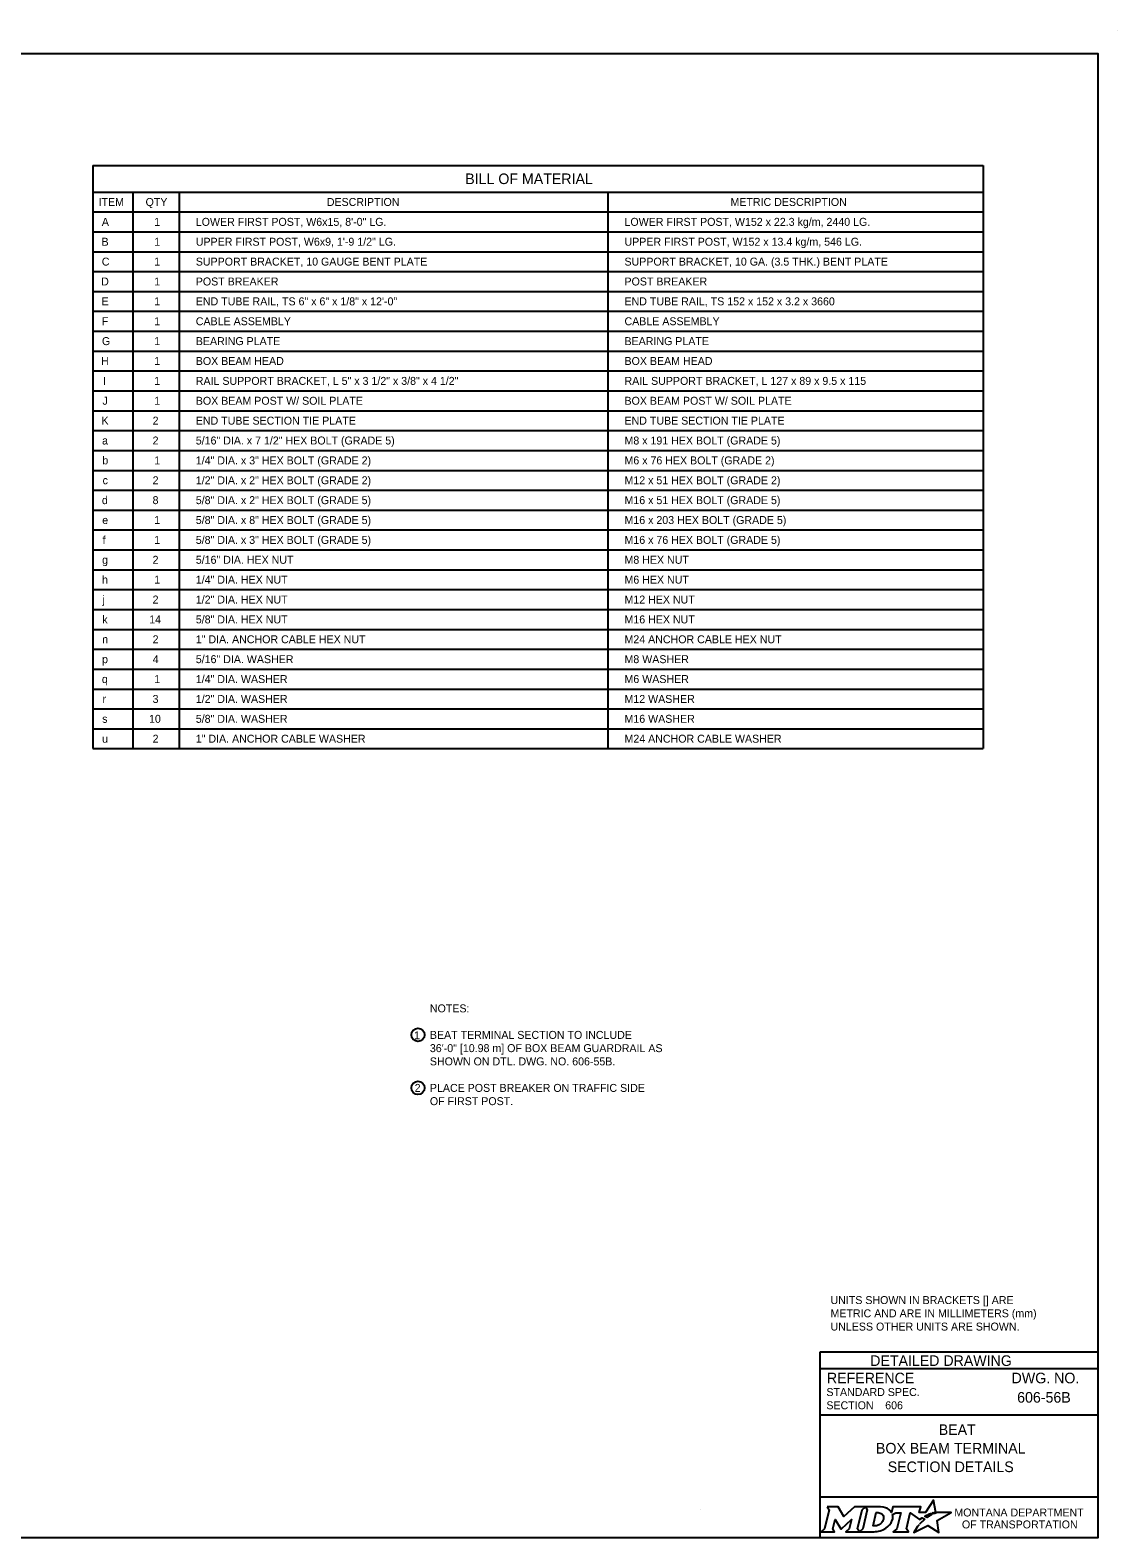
# Model space of a CAD drawing. Extents: x 49991.4 to 50021, y 49987.6 to 50011.4.
# Drawn here: x 50008.69 to 50016.9, y 49987.8 to 49999.18 of the extents above; entities that cross this region are included whole.
import ezdxf

# ---------------------------------------------------------------- set-up
doc = ezdxf.new("R2010")
doc.units = 0
for name, color, linetype in [('Default', 7, 'Continuous'), ('Level 1', 7, 'Continuous'), ('Level 2', 7, 'Continuous'), ('Level 5', 7, 'Continuous')]:
    doc.layers.add(name, color=color, linetype=linetype)

msp = doc.modelspace()

# ---------------------------------------------------------------- linework, layer by layer
at = {"layer": 'Default'}
for points in [[(50015.513, 49987.981), (50015.502, 49987.987), (50015.514, 49987.99), (50015.526, 49987.991), (50015.508, 49988.082), (50015.449, 49987.99), (50015.401, 49987.99), (50015.412, 49988.034), (50015.202, 49988.034), (50015.192, 49987.991), (50015.186, 49988)], [(50014.706, 49988.034), (50014.72, 49988.01), (50014.686, 49987.867), (50014.66, 49987.845), (50014.762, 49987.845), (50014.749, 49987.867), (50014.765, 49987.937), (50014.809, 49987.868), (50014.814, 49987.868), (50014.889, 49987.938), (50014.872, 49987.867), (50014.848, 49987.845), (50014.949, 49987.845), (50014.936, 49987.868), (50014.969, 49988.011)], [(50014.969, 49988.011), (50014.994, 49988.034), (50014.912, 49988.034), (50014.832, 49987.961), (50014.788, 49988.034), (50014.706, 49988.034)], [(50015.108, 49988.034), (50014.994, 49988.034), (50015.009, 49988.011), (50014.975, 49987.867), (50014.949, 49987.845), (50015.06, 49987.845)], [(50015.132, 49987.947), (50015.13, 49987.939), (50015.127, 49987.93), (50015.123, 49987.922), (50015.118, 49987.914), (50015.111, 49987.907), (50015.103, 49987.901), (50015.095, 49987.896), (50015.086, 49987.892), (50015.077, 49987.89), (50015.067, 49987.889), (50015.052, 49987.889), (50015.075, 49987.989), (50015.091, 49987.989), (50015.099, 49987.988), (50015.106, 49987.986), (50015.113, 49987.983), (50015.119, 49987.979), (50015.124, 49987.974), (50015.128, 49987.968), (50015.13, 49987.962), (50015.132, 49987.955), (50015.132, 49987.952), (50015.132, 49987.947)], [(50015.199, 49987.975), (50015.224, 49987.988), (50015.261, 49987.988), (50015.232, 49987.867), (50015.205, 49987.845), (50015.321, 49987.845), (50015.304, 49987.867), (50015.332, 49987.988), (50015.403, 49987.936), (50015.424, 49987.951), (50015.444, 49987.94)], [(50015.388, 49987.884), (50015.373, 49987.86), (50015.368, 49987.852), (50015.362, 49987.844), (50015.36, 49987.839), (50015.465, 49987.893), (50015.549, 49987.838), (50015.536, 49987.93), (50015.643, 49987.989), (50015.594, 49987.989), (50015.564, 49987.99), (50015.543, 49987.99), (50015.536, 49987.989), (50015.531, 49987.987), (50015.523, 49987.985), (50015.513, 49987.981)], [(50015.462, 49987.954), (50015.46, 49987.952), (50015.442, 49987.961), (50015.452, 49987.967), (50015.456, 49987.969), (50015.465, 49987.973), (50015.47, 49987.976), (50015.478, 49987.979), (50015.485, 49987.982), (50015.497, 49987.974), (50015.493, 49987.972), (50015.489, 49987.97), (50015.484, 49987.967), (50015.479, 49987.965), (50015.478, 49987.963), (50015.475, 49987.962), (50015.472, 49987.96), (50015.47, 49987.959), (50015.467, 49987.957), (50015.465, 49987.955), (50015.462, 49987.954)], [(50015.106, 49987.852), (50015.114, 49987.855), (50015.127, 49987.86), (50015.148, 49987.871)], [(50015.402, 49987.9), (50015.402, 49987.9)]]:
    msp.add_lwpolyline(points, dxfattribs=at)
for centre, radius, start, end in [((50015.087, 49987.973), 0.118, 300.9103, 339.1383), ((50015.131, 49987.955), 0.0709, 339.5329, 15.8582)]:
    msp.add_arc(centre, radius, start, end, dxfattribs=at)
for centre, major_axis, ratio, start_param, end_param in [((50015.106, 49987.986), (0.0834, -0.0037), 0.568097, 0.61298, 1.570796), ((50015.161, 49987.994), (0.0361, -0.0295), 0.469099, 1.225588, 1.570796), ((50015.433, 49987.93), (-0.0112, -0.0097), 0.021651, 3.157348, 6.283185), ((50015.06, 49987.993), (0, 0.148), 0.987302, 3.139398, 3.456847), ((50015.395, 49987.892), (-0.00694, -0.00806), 0.008222, 0, 3.137361), ((50015.412, 49987.911), (-0.0098, -0.0102), 0.016458, 3.141593, 6.279097)]:
    msp.add_ellipse(centre, major_axis=major_axis, ratio=ratio, start_param=start_param, end_param=end_param, dxfattribs=at)
at = {"layer": 'Level 1'}
msp.add_line((50016.9, 49999.176), (50016.9, 49999.176), dxfattribs=at)
msp.add_lwpolyline([(49999.384, 49998.999), (50016.75, 49998.999), (50016.75, 49987.799), (49999.384, 49987.799)], close=True, dxfattribs=at)
at = {"layer": 'Level 2'}
for p, q in [((50009.164, 49998.154), (50009.164, 49993.754)), ((50009.164, 49998.154), (50015.883, 49998.154)), ((50015.883, 49998.154), (50015.883, 49993.754)), ((50009.164, 49997.954), (50013.049, 49997.954)), ((50009.464, 49997.954), (50009.464, 49993.754)), ((50009.814, 49997.954), (50009.814, 49993.754)), ((50013.049, 49997.954), (50015.883, 49997.954)), ((50013.049, 49997.954), (50013.049, 49993.754)), ((50009.164, 49997.804), (50013.049, 49997.804)), ((50013.049, 49997.804), (50015.883, 49997.804)), ((50009.164, 49997.654), (50013.049, 49997.654)), ((50013.049, 49997.654), (50015.883, 49997.654)), ((50009.164, 49997.504), (50013.049, 49997.504)), ((50013.049, 49997.504), (50015.883, 49997.504)), ((50009.164, 49997.354), (50013.049, 49997.354)), ((50013.049, 49997.354), (50015.883, 49997.354)), ((50009.164, 49997.204), (50013.049, 49997.204)), ((50013.049, 49997.204), (50015.883, 49997.204)), ((50009.164, 49997.054), (50013.049, 49997.054)), ((50013.049, 49997.054), (50015.883, 49997.054)), ((50009.164, 49996.904), (50013.049, 49996.904)), ((50013.049, 49996.904), (50015.883, 49996.904)), ((50009.164, 49996.754), (50013.049, 49996.754)), ((50013.049, 49996.754), (50015.883, 49996.754)), ((50009.164, 49996.604), (50013.049, 49996.604)), ((50013.049, 49996.604), (50015.883, 49996.604)), ((50009.164, 49996.454), (50013.049, 49996.454)), ((50013.049, 49996.454), (50015.883, 49996.454)), ((50009.164, 49996.304), (50013.049, 49996.304)), ((50013.049, 49996.304), (50015.883, 49996.304)), ((50009.164, 49996.154), (50013.049, 49996.154)), ((50013.049, 49996.154), (50015.883, 49996.154)), ((50009.164, 49996.004), (50013.049, 49996.004)), ((50013.049, 49996.004), (50015.883, 49996.004)), ((50009.164, 49995.854), (50013.049, 49995.854)), ((50013.049, 49995.854), (50015.883, 49995.854)), ((50009.164, 49995.704), (50013.049, 49995.704)), ((50013.049, 49995.704), (50015.883, 49995.704)), ((50009.164, 49995.554), (50013.049, 49995.554)), ((50013.049, 49995.554), (50015.883, 49995.554)), ((50009.164, 49995.404), (50013.049, 49995.404)), ((50013.049, 49995.404), (50015.883, 49995.404)), ((50009.164, 49995.254), (50013.049, 49995.254)), ((50013.049, 49995.254), (50015.883, 49995.254)), ((50009.164, 49995.104), (50013.049, 49995.104)), ((50013.049, 49995.104), (50015.883, 49995.104)), ((50009.164, 49994.954), (50013.049, 49994.954)), ((50013.049, 49994.954), (50015.883, 49994.954)), ((50009.164, 49994.804), (50013.049, 49994.804)), ((50013.049, 49994.804), (50015.883, 49994.804)), ((50009.164, 49994.654), (50013.049, 49994.654)), ((50013.049, 49994.654), (50015.883, 49994.654)), ((50009.164, 49994.504), (50013.049, 49994.504)), ((50013.049, 49994.504), (50015.883, 49994.504)), ((50009.164, 49994.354), (50013.049, 49994.354)), ((50013.049, 49994.354), (50015.883, 49994.354)), ((50009.164, 49994.204), (50013.049, 49994.204)), ((50013.049, 49994.204), (50015.883, 49994.204)), ((50009.164, 49994.054), (50013.049, 49994.054)), ((50013.049, 49994.054), (50015.883, 49994.054)), ((50009.164, 49993.904), (50013.049, 49993.904)), ((50013.049, 49993.904), (50015.883, 49993.904)), ((50009.164, 49993.754), (50013.049, 49993.754)), ((50013.049, 49993.754), (50015.883, 49993.754)), ((50013.746, 49988.012), (50013.746, 49988.012))]:
    msp.add_line(p, q, dxfattribs=at)
for centre in [(50011.617, 49991.594), (50011.617, 49991.194)]:
    msp.add_circle(centre, 0.05, dxfattribs=at)
at = {"layer": 'Level 5'}
for p, q in [((50016.75, 49989.199), (50014.65, 49989.199)), ((50014.65, 49989.199), (50014.65, 49987.799)), ((50016.75, 49989.074), (50014.65, 49989.074)), ((50016.386, 49988.859), (50016.386, 49988.859)), ((50016.75, 49988.724), (50014.65, 49988.724)), ((50015.144, 49988.799), (50015.144, 49988.799)), ((50015.7, 49988.475), (50015.7, 49988.475)), ((50016.75, 49988.106), (50014.65, 49988.106))]:
    msp.add_line(p, q, dxfattribs=at)

# ---------------------------------------------------------------- texts
at = {"layer": 'Default'}
for s, p in [('MONTANA DEPARTMENT', (50015.666, 49987.96)), ('OF TRANSPORTATION', (50015.723, 49987.87))]:
    msp.add_text(s, height=0.06, dxfattribs=at).set_placement(p)
at = {"layer": 'Level 2'}
for s, height, p in [('BILL OF MATERIAL', 0.08, (50011.974, 49998.014)), ('ITEM', 0.06, (50009.206, 49997.849)), ('QTY', 0.06, (50009.561, 49997.849)), ('DESCRIPTION', 0.06, (50010.929, 49997.849)), ('METRIC DESCRIPTION', 0.06, (50013.976, 49997.849)), ('  A', 0.06, (50009.186, 49997.699)), ('1', 0.06, (50009.626, 49997.699)), ('LOWER FIRST POST, W6x15, 8\'-0" LG.', 0.06, (50009.94, 49997.699)), ('LOWER FIRST POST, W152 x 22.3 kg/m, 2440 LG.', 0.06, (50013.176, 49997.699)), ('  B', 0.06, (50009.184, 49997.549)), ('1', 0.06, (50009.626, 49997.549)), ('UPPER FIRST POST, W6x9, 1\'-9 1/2" LG.', 0.06, (50009.94, 49997.549)), ('UPPER FIRST POST, W152 x 13.4 kg/m, 546 LG.', 0.06, (50013.176, 49997.549)), ('  C', 0.06, (50009.186, 49997.399)), ('1', 0.06, (50009.626, 49997.399)), ('SUPPORT BRACKET, 10 GAUGE BENT PLATE', 0.06, (50009.94, 49997.399)), ('SUPPORT BRACKET, 10 GA. (3.5 THK.) BENT PLATE', 0.06, (50013.176, 49997.399)), ('  D', 0.06, (50009.181, 49997.249)), ('1', 0.06, (50009.626, 49997.249)), ('POST BREAKER', 0.06, (50009.94, 49997.249)), ('POST BREAKER', 0.06, (50013.176, 49997.249)), ('  E', 0.06, (50009.184, 49997.099)), ('1', 0.06, (50009.626, 49997.099)), ('END TUBE RAIL, TS 6" x 6" x 1/8" x 12\'-0" ', 0.06, (50009.94, 49997.099)), ('END TUBE RAIL, TS 152 x 152 x 3.2 x 3660', 0.06, (50013.176, 49997.099)), ('  F', 0.06, (50009.186, 49996.949)), ('1', 0.06, (50009.626, 49996.949)), ('CABLE ASSEMBLY', 0.06, (50009.94, 49996.949)), ('CABLE ASSEMBLY', 0.06, (50013.176, 49996.949)), ('  G', 0.06, (50009.187, 49996.799)), ('1', 0.06, (50009.626, 49996.799)), ('BEARING PLATE', 0.06, (50009.94, 49996.799)), ('BEARING PLATE', 0.06, (50013.176, 49996.799)), ('  H', 0.06, (50009.18, 49996.649)), ('1', 0.06, (50009.626, 49996.649)), ('BOX BEAM HEAD', 0.06, (50009.94, 49996.649)), ('BOX BEAM HEAD', 0.06, (50013.176, 49996.649)), ('  I', 0.06, (50009.195, 49996.499)), ('1', 0.06, (50009.626, 49996.499)), ('RAIL SUPPORT BRACKET, L 5" x 3 1/2" x 3/8" x 4 1/2"', 0.06, (50009.94, 49996.499)), ('RAIL SUPPORT BRACKET, L 127 x 89 x 9.5 x 115', 0.06, (50013.176, 49996.499)), ('  J', 0.06, (50009.191, 49996.349)), ('1', 0.06, (50009.626, 49996.349)), ('BOX BEAM POST W/ SOIL PLATE', 0.06, (50009.94, 49996.349)), ('BOX BEAM POST W/ SOIL PLATE', 0.06, (50013.176, 49996.349)), ('  K', 0.06, (50009.184, 49996.199)), ('2', 0.06, (50009.614, 49996.199)), ('END TUBE SECTION TIE PLATE', 0.06, (50009.94, 49996.199)), ('END TUBE SECTION TIE PLATE', 0.06, (50013.176, 49996.199)), ('  a', 0.06, (50009.188, 49996.049)), ('2', 0.06, (50009.614, 49996.049)), ('5/16" DIA. x 7 1/2" HEX BOLT (GRADE 5)', 0.06, (50009.94, 49996.049)), ('M8 x 191 HEX BOLT (GRADE 5)', 0.06, (50013.176, 49996.049)), ('  b', 0.06, (50009.19, 49995.899)), ('1', 0.06, (50009.626, 49995.899)), ('1/4" DIA. x 3" HEX BOLT (GRADE 2)', 0.06, (50009.94, 49995.899)), ('M6 x 76 HEX BOLT (GRADE 2)', 0.06, (50013.176, 49995.899)), ('  c', 0.06, (50009.192, 49995.749)), ('2', 0.06, (50009.614, 49995.749)), ('1/2" DIA. x 2" HEX BOLT (GRADE 2)', 0.06, (50009.94, 49995.749)), ('M12 x 51 HEX BOLT (GRADE 2)', 0.06, (50013.176, 49995.749)), ('  d', 0.06, (50009.187, 49995.599)), ('5/8" DIA. x 2" HEX BOLT (GRADE 5)', 0.06, (50009.94, 49995.599)), ('M16 x 51 HEX BOLT (GRADE 5)', 0.06, (50013.176, 49995.599)), ('8', 0.06, (50009.614, 49995.599)), ('  e', 0.06, (50009.189, 49995.449)), ('1', 0.06, (50009.626, 49995.449)), ('5/8" DIA. x 8" HEX BOLT (GRADE 5)', 0.06, (50009.94, 49995.449)), ('M16 x 203 HEX BOLT (GRADE 5)', 0.06, (50013.176, 49995.449)), ('  f', 0.06, (50009.192, 49995.299)), ('1', 0.06, (50009.626, 49995.299)), ('5/8" DIA. x 3" HEX BOLT (GRADE 5)', 0.06, (50009.94, 49995.299)), ('M16 x 76 HEX BOLT (GRADE 5)', 0.06, (50013.176, 49995.299)), ('2', 0.06, (50009.614, 49995.149)), ('5/16" DIA. HEX NUT', 0.06, (50009.94, 49995.149)), ('M8 HEX NUT', 0.06, (50013.176, 49995.149)), ('  g', 0.06, (50009.188, 49995.149)), ('  h', 0.06, (50009.188, 49994.999)), ('1', 0.06, (50009.626, 49994.999)), ('1/4" DIA. HEX NUT', 0.06, (50009.94, 49994.999)), ('M6 HEX NUT', 0.06, (50013.176, 49994.999)), ('  j', 0.06, (50009.191, 49994.849)), ('2', 0.06, (50009.614, 49994.849)), ('1/2" DIA. HEX NUT', 0.06, (50009.94, 49994.849)), ('M12 HEX NUT', 0.06, (50013.176, 49994.849)), ('  k', 0.06, (50009.19, 49994.699)), ('14', 0.06, (50009.588, 49994.699)), ('5/8" DIA. HEX NUT', 0.06, (50009.94, 49994.699)), ('M16 HEX NUT', 0.06, (50013.176, 49994.699)), ('  n', 0.06, (50009.189, 49994.549)), ('2', 0.06, (50009.614, 49994.549)), ('1" DIA. ANCHOR CABLE HEX NUT', 0.06, (50009.94, 49994.549)), ('M24 ANCHOR CABLE HEX NUT', 0.06, (50013.176, 49994.549)), ('  p', 0.06, (50009.188, 49994.399)), ('4', 0.06, (50009.615, 49994.399)), ('5/16" DIA. WASHER', 0.06, (50009.94, 49994.399)), ('M8 WASHER', 0.06, (50013.176, 49994.399)), ('1', 0.06, (50009.626, 49994.249)), ('1/4" DIA. WASHER', 0.06, (50009.94, 49994.249)), ('M6 WASHER', 0.06, (50013.176, 49994.249)), ('  q', 0.06, (50009.187, 49994.249)), ('  r', 0.06, (50009.191, 49994.099)), ('3', 0.06, (50009.614, 49994.099)), ('1/2" DIA. WASHER', 0.06, (50009.94, 49994.099)), ('M12 WASHER', 0.06, (50013.176, 49994.099)), ('  s', 0.06, (50009.189, 49993.949)), ('10', 0.06, (50009.587, 49993.949)), ('5/8" DIA. WASHER', 0.06, (50009.94, 49993.949)), ('M16 WASHER', 0.06, (50013.176, 49993.949)), ('  u', 0.06, (50009.188, 49993.799)), ('2', 0.06, (50009.614, 49993.799)), ('1" DIA. ANCHOR CABLE WASHER', 0.06, (50009.94, 49993.799)), ('M24 ANCHOR CABLE WASHER', 0.06, (50013.176, 49993.799)), ('NOTES:', 0.06, (50011.707, 49991.764)), ('1', 0.06, (50011.588, 49991.561)), ('BEAT TERMINAL SECTION TO INCLUDE', 0.06, (50011.707, 49991.564)), ('36\'-0" [10.98 m] OF BOX BEAM GUARDRAIL AS', 0.06, (50011.707, 49991.464)), ('SHOWN ON DTL. DWG. NO. 606-55B.', 0.06, (50011.707, 49991.364)), ('2', 0.06, (50011.592, 49991.164)), ('OF FIRST POST.', 0.06, (50011.707, 49991.064)), ('PLACE POST BREAKER ON TRAFFIC SIDE', 0.06, (50011.707, 49991.164)), ('UNITS SHOWN IN BRACKETS [] ARE ', 0.06, (50014.731, 49989.563)), ('METRIC AND ARE IN MILLIMETERS (mm) ', 0.06, (50014.731, 49989.463)), ('UNLESS OTHER UNITS ARE SHOWN.', 0.06, (50014.731, 49989.363)), ('606-56B', 0.08, (50016.14, 49988.819)), ('606', 0.06, (50015.144, 49988.769)), ('BEAT', 0.08, (50015.548, 49988.575)), ('BOX BEAM TERMINAL', 0.08, (50015.074, 49988.435)), ('SECTION DETAILS', 0.08, (50015.163, 49988.295))]:
    msp.add_text(s, height=height, dxfattribs=at).set_placement(p)
at = {"layer": 'Level 5'}
for s, height, p in [('DETAILED DRAWING', 0.0799, (50015.031, 49989.096)), ('REFERENCE', 0.08, (50014.704, 49988.965)), ('DWG. NO.', 0.08, (50016.098, 49988.965)), ('STANDARD SPEC.', 0.06, (50014.7, 49988.869)), ('SECTION', 0.06, (50014.7, 49988.769))]:
    msp.add_text(s, height=height, dxfattribs=at).set_placement(p)

doc.saveas('drawing.dxf')
